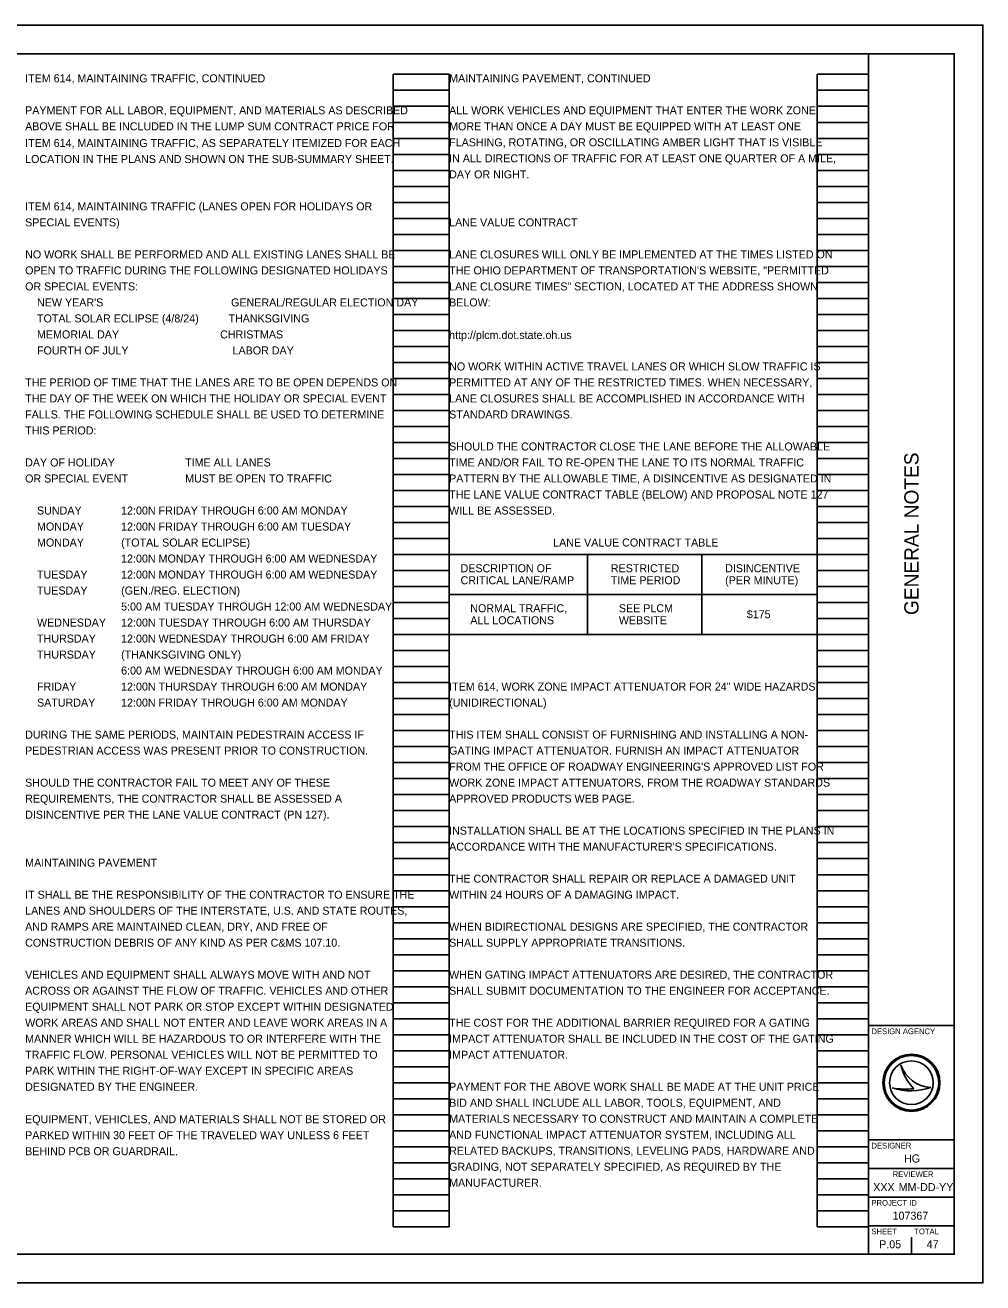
# Model space of a CAD drawing. Extents: x 0 to 34, y 0 to 22.
# Drawn here: x 17.24 to 34, y 0 to 22 of the extents above; entities that cross this region are included whole.
import ezdxf

# ---------------------------------------------------------------- set-up
doc = ezdxf.new("R2010")
doc.units = 0
for name, color, linetype in [('SH_Border', 7, 'Continuous'), ('SH_Cut_Line', 7, 'Continuous'), ('SH_Data', 7, 'Continuous'), ('SH_Text', 7, 'Continuous')]:
    doc.layers.add(name, color=color, linetype=linetype)

msp = doc.modelspace()

# ---------------------------------------------------------------- linework, layer by layer
at = {"layer": 'SH_Border'}
for p, q in [((32, 0.5), (32, 21.5)), ((32, 4.5), (33.5, 4.5)), ((32, 2.5), (33.5, 2.5)), ((32, 2), (33.5, 2)), ((32, 1.5), (33.5, 1.5)), ((32, 1), (33.5, 1))]:
    msp.add_line(p, q, dxfattribs=at)
msp.add_lwpolyline([(1.5, 21.5), (33.5, 21.5), (33.5, 0.5), (1.5, 0.5)], close=True, dxfattribs=at)
at = {"layer": 'SH_Cut_Line'}
msp.add_lwpolyline([(0, 0), (34, 0), (34, 22), (0, 22)], close=True, dxfattribs=at)
at = {"layer": 'SH_Data'}
for p, q in [((23.68, 0.98), (23.68, 21.14)), ((23.68, 21.14), (24.66, 21.14)), ((24.66, 0.98), (24.66, 21.14)), ((31.1, 0.98), (31.1, 21.14)), ((31.1, 21.14), (32, 21.14)), ((32, 0.98), (32, 21.14)), ((23.68, 20.86), (24.66, 20.86)), ((31.1, 20.86), (32, 20.86)), ((23.68, 20.58), (24.66, 20.58)), ((31.1, 20.58), (32, 20.58)), ((23.68, 20.3), (24.66, 20.3)), ((31.1, 20.3), (32, 20.3)), ((23.68, 20.02), (24.66, 20.02)), ((31.1, 20.02), (32, 20.02)), ((23.68, 19.74), (24.66, 19.74)), ((31.1, 19.74), (32, 19.74)), ((23.68, 19.46), (24.66, 19.46)), ((31.1, 19.46), (32, 19.46)), ((23.68, 19.18), (24.66, 19.18)), ((31.1, 19.18), (32, 19.18)), ((23.68, 18.9), (24.66, 18.9)), ((31.1, 18.9), (32, 18.9)), ((23.68, 18.62), (24.66, 18.62)), ((31.1, 18.62), (32, 18.62)), ((23.68, 18.34), (24.66, 18.34)), ((31.1, 18.34), (32, 18.34)), ((23.68, 18.06), (24.66, 18.06)), ((31.1, 18.06), (32, 18.06)), ((23.68, 17.78), (24.66, 17.78)), ((31.1, 17.78), (32, 17.78)), ((23.68, 17.5), (24.66, 17.5)), ((31.1, 17.5), (32, 17.5)), ((23.68, 17.22), (24.66, 17.22)), ((31.1, 17.22), (32, 17.22)), ((23.68, 16.94), (24.66, 16.94)), ((31.1, 16.94), (32, 16.94)), ((23.68, 16.66), (24.66, 16.66)), ((31.1, 16.66), (32, 16.66)), ((23.68, 16.38), (24.66, 16.38)), ((31.1, 16.38), (32, 16.38)), ((23.68, 16.1), (24.66, 16.1)), ((31.1, 16.1), (32, 16.1)), ((23.68, 15.82), (24.66, 15.82)), ((31.1, 15.82), (32, 15.82)), ((23.68, 15.54), (24.66, 15.54)), ((31.1, 15.54), (32, 15.54)), ((23.68, 15.26), (24.66, 15.26)), ((31.1, 15.26), (32, 15.26)), ((23.68, 14.98), (24.66, 14.98)), ((31.1, 14.98), (32, 14.98)), ((23.68, 14.7), (24.66, 14.7)), ((31.1, 14.7), (32, 14.7)), ((23.68, 14.42), (24.66, 14.42)), ((31.1, 14.42), (32, 14.42)), ((23.68, 14.14), (24.66, 14.14)), ((31.1, 14.14), (32, 14.14)), ((23.68, 13.86), (24.66, 13.86)), ((31.1, 13.86), (32, 13.86)), ((23.68, 13.58), (24.66, 13.58)), ((31.1, 13.58), (32, 13.58)), ((23.68, 13.3), (24.66, 13.3)), ((31.1, 13.3), (32, 13.3)), ((23.68, 13.02), (24.66, 13.02)), ((31.1, 13.02), (32, 13.02)), ((23.68, 12.74), (24.66, 12.74)), ((31.1, 12.74), (32, 12.74)), ((23.68, 12.46), (24.66, 12.46)), ((31.1, 12.46), (32, 12.46)), ((23.68, 12.18), (24.66, 12.18)), ((31.1, 12.18), (32, 12.18)), ((23.68, 11.9), (24.66, 11.9)), ((31.1, 11.9), (32, 11.9)), ((23.68, 11.62), (24.66, 11.62)), ((31.1, 11.62), (32, 11.62)), ((23.68, 11.34), (24.66, 11.34)), ((31.1, 11.34), (32, 11.34)), ((23.68, 11.06), (24.66, 11.06)), ((31.1, 11.06), (32, 11.06)), ((23.68, 10.78), (24.66, 10.78)), ((31.1, 10.78), (32, 10.78)), ((23.68, 10.5), (24.66, 10.5)), ((31.1, 10.5), (32, 10.5)), ((23.68, 10.22), (24.66, 10.22)), ((31.1, 10.22), (32, 10.22)), ((23.68, 9.94), (24.66, 9.94)), ((31.1, 9.94), (32, 9.94)), ((23.68, 9.66), (24.66, 9.66)), ((31.1, 9.66), (32, 9.66)), ((23.68, 9.38), (24.66, 9.38)), ((31.1, 9.38), (32, 9.38)), ((23.68, 9.1), (24.66, 9.1)), ((31.1, 9.1), (32, 9.1)), ((23.68, 8.82), (24.66, 8.82)), ((31.1, 8.82), (32, 8.82)), ((23.68, 8.54), (24.66, 8.54)), ((31.1, 8.54), (32, 8.54)), ((23.68, 8.26), (24.66, 8.26)), ((31.1, 8.26), (32, 8.26)), ((23.68, 7.98), (24.66, 7.98)), ((31.1, 7.98), (32, 7.98)), ((23.68, 7.7), (24.66, 7.7)), ((31.1, 7.7), (32, 7.7)), ((23.68, 7.42), (24.66, 7.42)), ((31.1, 7.42), (32, 7.42)), ((23.68, 7.14), (24.66, 7.14)), ((31.1, 7.14), (32, 7.14)), ((23.68, 6.86), (24.66, 6.86)), ((31.1, 6.86), (32, 6.86)), ((23.68, 6.58), (24.66, 6.58)), ((31.1, 6.58), (32, 6.58)), ((23.68, 6.3), (24.66, 6.3)), ((31.1, 6.3), (32, 6.3)), ((23.68, 6.02), (24.66, 6.02)), ((31.1, 6.02), (32, 6.02)), ((23.68, 5.74), (24.66, 5.74)), ((31.1, 5.74), (32, 5.74)), ((23.68, 5.46), (24.66, 5.46)), ((31.1, 5.46), (32, 5.46)), ((23.68, 5.18), (24.66, 5.18)), ((31.1, 5.18), (32, 5.18)), ((23.68, 4.9), (24.66, 4.9)), ((31.1, 4.9), (32, 4.9)), ((23.68, 4.62), (24.66, 4.62)), ((31.1, 4.62), (32, 4.62)), ((23.68, 4.34), (24.66, 4.34)), ((31.1, 4.34), (32, 4.34)), ((23.68, 4.06), (24.66, 4.06)), ((31.1, 4.06), (32, 4.06)), ((23.68, 3.78), (24.66, 3.78)), ((31.1, 3.78), (32, 3.78)), ((32.567, 3.81), (32.567, 3.81)), ((23.68, 3.5), (24.66, 3.5)), ((31.1, 3.5), (32, 3.5)), ((32.417, 3.41), (32.417, 3.41)), ((32.75, 3.5), (32.75, 3.5)), ((33.087, 3.419), (33.087, 3.419)), ((23.68, 3.22), (24.66, 3.22)), ((31.1, 3.22), (32, 3.22)), ((23.68, 2.94), (24.66, 2.94)), ((31.1, 2.94), (32, 2.94)), ((23.68, 2.66), (24.66, 2.66)), ((31.1, 2.66), (32, 2.66)), ((23.68, 2.38), (24.66, 2.38)), ((31.1, 2.38), (32, 2.38)), ((23.68, 2.1), (24.66, 2.1)), ((31.1, 2.1), (32, 2.1)), ((23.68, 1.82), (24.66, 1.82)), ((31.1, 1.82), (32, 1.82)), ((23.68, 1.54), (24.66, 1.54)), ((31.1, 1.54), (32, 1.54)), ((23.68, 1.26), (24.66, 1.26)), ((31.1, 1.26), (32, 1.26)), ((23.68, 0.98), (24.66, 0.98)), ((31.1, 0.98), (32, 0.98)), ((32.375, 0.675), (32.375, 0.675)), ((32.75, 0.5), (32.75, 0.8))]:
    msp.add_line(p, q, dxfattribs=at)
for radius in [0.5, 0.477, 0.477, 0.382]:
    msp.add_circle((32.75, 3.5), radius, dxfattribs=at)
for centre, radius, start, end in [((33.116, 3.998), 0.58, 198.9257, 198.9319), ((33.347, 3.97), 0.796, 191.6379, 191.6421), ((33.116, 3.998), 0.58, 198.9319, 267.1657), ((33.347, 3.97), 0.796, 191.6421, 226.0947), ((32.739, 4.37), 1.013, 251.4576, 290.0832), ((32.648, 4.654), 1.266, 259.4964, 259.4995), ((32.739, 4.37), 1.013, 251.4527, 251.4576), ((32.648, 4.654), 1.266, 259.4995, 276.6672)]:
    msp.add_arc(centre, radius, start, end, dxfattribs=at)
at = {"layer": 'SH_Text'}
for p, q in [((27.08, 12.74), (27.08, 11.34)), ((29.08, 12.74), (29.08, 11.34)), ((24.66, 12.04), (31.1, 12.04))]:
    msp.add_line(p, q, dxfattribs=at)
msp.add_lwpolyline([(24.66, 12.74), (31.1, 12.74), (31.1, 11.34), (24.66, 11.34)], close=True, dxfattribs=at)

# ---------------------------------------------------------------- texts
at = {"layer": 'SH_Data'}
msp.add_text('GENERAL NOTES', height=0.25, rotation=90, dxfattribs=at).set_placement((32.875, 11.682))
for s, height, p in [('DESIGN AGENCY', 0.1, (32.05, 4.35)), ('DESIGNER', 0.1, (32.05, 2.35)), ('HG', 0.14, (32.62, 2.105)), ('REVIEWER', 0.1, (32.422, 1.85)), ('XXX', 0.14, (32.081, 1.605)), ('MM-DD-YY', 0.14, (32.527, 1.605)), ('PROJECT ID', 0.1, (32.05, 1.35)), ('107367', 0.14, (32.42, 1.105)), ('SHEET', 0.1, (32.05, 0.85)), ('TOTAL', 0.1, (32.8, 0.85)), ('P.05', 0.14, (32.185, 0.605)), ('47', 0.14, (33.018, 0.605))]:
    msp.add_text(s, height=height, dxfattribs=at).set_placement(p)
at = {"layer": 'SH_Text'}
for s, p in [('ITEM 614, MAINTAINING TRAFFIC, CONTINUED', (17.24, 21)), ('MAINTAINING PAVEMENT, CONTINUED', (24.66, 21)), ('PAYMENT FOR ALL LABOR, EQUIPMENT, AND MATERIALS AS DESCRIBED', (17.24, 20.44)), ('ALL WORK VEHICLES AND EQUIPMENT THAT ENTER THE WORK ZONE', (24.66, 20.44)), ('ABOVE SHALL BE INCLUDED IN THE LUMP SUM CONTRACT PRICE FOR', (17.24, 20.16)), ('MORE THAN ONCE A DAY MUST BE EQUIPPED WITH AT LEAST ONE', (24.66, 20.16)), ('FLASHING, ROTATING, OR OSCILLATING AMBER LIGHT THAT IS VISIBLE', (24.66, 19.88)), ('ITEM 614, MAINTAINING TRAFFIC, AS SEPARATELY ITEMIZED FOR EACH', (17.24, 19.868)), ('LOCATION IN THE PLANS AND SHOWN ON THE SUB-SUMMARY SHEET.', (17.24, 19.588)), ('IN ALL DIRECTIONS OF TRAFFIC FOR AT LEAST ONE QUARTER OF A MILE,', (24.66, 19.6)), ('DAY OR NIGHT.', (24.66, 19.32)), ('ITEM 614, MAINTAINING TRAFFIC (LANES OPEN FOR HOLIDAYS OR', (17.24, 18.76)), ('SPECIAL EVENTS)', (17.24, 18.48)), ('LANE VALUE CONTRACT', (24.66, 18.48)), ('NO WORK SHALL BE PERFORMED AND ALL EXISTING LANES SHALL BE', (17.24, 17.92)), ('LANE CLOSURES WILL ONLY BE IMPLEMENTED AT THE TIMES LISTED ON', (24.66, 17.92)), ('OPEN TO TRAFFIC DURING THE FOLLOWING DESIGNATED HOLIDAYS', (17.24, 17.64)), ('THE OHIO DEPARTMENT OF TRANSPORTATION\'S WEBSITE, "PERMITTED', (24.66, 17.64)), ('OR SPECIAL EVENTS:', (17.24, 17.36)), ('LANE CLOSURE TIMES" SECTION, LOCATED AT THE ADDRESS SHOWN', (24.66, 17.36)), ("    NEW YEAR'S                                           GENERAL/REGULAR ELECTION DAY", (17.24, 17.08)), ('BELOW:', (24.66, 17.08)), ('    TOTAL SOLAR ECLIPSE (4/8/24)          THANKSGIVING', (17.24, 16.8)), ('    MEMORIAL DAY                  ', (17.24, 16.52)), (' CHRISTMAS', (20.6, 16.52)), ('http://plcm.dot.state.oh.us', (24.66, 16.51)), ('    FOURTH OF JULY                                   LABOR DAY', (17.24, 16.24)), ('NO WORK WITHIN ACTIVE TRAVEL LANES OR WHICH SLOW TRAFFIC IS', (24.66, 15.96)), ('THE PERIOD OF TIME THAT THE LANES ARE TO BE OPEN DEPENDS ON', (17.24, 15.68)), ('PERMITTED AT ANY OF THE RESTRICTED TIMES. WHEN NECESSARY,', (24.66, 15.68)), ('THE DAY OF THE WEEK ON WHICH THE HOLIDAY OR SPECIAL EVENT', (17.24, 15.4)), ('LANE CLOSURES SHALL BE ACCOMPLISHED IN ACCORDANCE WITH', (24.66, 15.4)), ('FALLS. THE FOLLOWING SCHEDULE SHALL BE USED TO DETERMINE', (17.24, 15.12)), ('STANDARD DRAWINGS.', (24.66, 15.12)), ('THIS PERIOD:', (17.24, 14.84)), ('SHOULD THE CONTRACTOR CLOSE THE LANE BEFORE THE ALLOWABLE', (24.66, 14.56)), ('DAY OF HOLIDAY', (17.24, 14.28)), ('TIME ALL LANES', (20.04, 14.28)), ('TIME AND/OR FAIL TO RE-OPEN THE LANE TO ITS NORMAL TRAFFIC', (24.66, 14.28)), ('OR SPECIAL EVENT', (17.24, 14)), ('MUST BE OPEN TO TRAFFIC', (20.04, 14)), ('PATTERN BY THE ALLOWABLE TIME, A DISINCENTIVE AS DESIGNATED IN', (24.66, 14)), ('THE LANE VALUE CONTRACT TABLE (BELOW) AND PROPOSAL NOTE 127', (24.66, 13.72)), ('    SUNDAY', (17.24, 13.44)), ('12:00N FRIDAY THROUGH 6:00 AM MONDAY', (18.92, 13.44)), ('WILL BE ASSESSED.', (24.66, 13.44)), ('    MONDAY', (17.24, 13.16)), ('12:00N FRIDAY THROUGH 6:00 AM TUESDAY', (18.92, 13.16)), ('    MONDAY', (17.24, 12.88)), ('(TOTAL SOLAR ECLIPSE)', (18.92, 12.88)), ('                                   LANE VALUE CONTRACT TABLE', (24.66, 12.88)), ('12:00N MONDAY THROUGH 6:00 AM WEDNESDAY', (18.92, 12.6)), ('DESCRIPTION OF', (24.86, 12.43)), ('RESTRICTED', (27.49, 12.43)), ('DISINCENTIVE', (29.49, 12.43)), ('    TUESDAY', (17.24, 12.32)), ('12:00N MONDAY THROUGH 6:00 AM WEDNESDAY', (18.92, 12.32)), ('CRITICAL LANE/RAMP', (24.86, 12.22)), ('TIME PERIOD', (27.49, 12.22)), ('(PER MINUTE)', (29.49, 12.22)), ('    TUESDAY', (17.24, 12.04)), ('(GEN./REG. ELECTION)', (18.92, 12.04)), ('5:00 AM TUESDAY THROUGH 12:00 AM WEDNESDAY', (18.92, 11.76)), ('ALL LOCATIONS', (25.03, 11.52)), ('NORMAL TRAFFIC,', (25.03, 11.73)), ('WEBSITE', (27.63, 11.52)), ('SEE PLCM', (27.63, 11.73)), ('$175', (29.869, 11.625)), ('    WEDNESDAY', (17.24, 11.48)), ('12:00N TUESDAY THROUGH 6:00 AM THURSDAY', (18.92, 11.48)), ('    THURSDAY', (17.24, 11.2)), ('12:00N WEDNESDAY THROUGH 6:00 AM FRIDAY', (18.92, 11.2)), ('    THURSDAY', (17.24, 10.92)), ('(THANKSGIVING ONLY)', (18.92, 10.92)), ('6:00 AM WEDNESDAY THROUGH 6:00 AM MONDAY', (18.92, 10.64)), ('    FRIDAY', (17.24, 10.36)), ('12:00N THURSDAY THROUGH 6:00 AM MONDAY', (18.92, 10.36)), ('ITEM 614, WORK ZONE IMPACT ATTENUATOR FOR 24" WIDE HAZARDS', (24.66, 10.36)), ('    SATURDAY', (17.24, 10.08)), ('12:00N FRIDAY THROUGH 6:00 AM MONDAY', (18.92, 10.08)), ('(UNIDIRECTIONAL)', (24.66, 10.08)), ('DURING THE SAME PERIODS, MAINTAIN PEDESTRAIN ACCESS IF', (17.24, 9.52)), ('THIS ITEM SHALL CONSIST OF FURNISHING AND INSTALLING A NON-', (24.66, 9.52)), ('PEDESTRIAN ACCESS WAS PRESENT PRIOR TO CONSTRUCTION.', (17.24, 9.24)), ('GATING IMPACT ATTENUATOR. FURNISH AN IMPACT ATTENUATOR', (24.66, 9.24)), ("FROM THE OFFICE OF ROADWAY ENGINEERING'S APPROVED LIST FOR", (24.66, 8.96)), ('SHOULD THE CONTRACTOR FAIL TO MEET ANY OF THESE', (17.24, 8.68)), ('WORK ZONE IMPACT ATTENUATORS, FROM THE ROADWAY STANDARDS', (24.66, 8.68)), ('REQUIREMENTS, THE CONTRACTOR SHALL BE ASSESSED A', (17.24, 8.4)), ('APPROVED PRODUCTS WEB PAGE.', (24.66, 8.4)), ('DISINCENTIVE PER THE LANE VALUE CONTRACT (PN 127).', (17.24, 8.12)), ('INSTALLATION SHALL BE AT THE LOCATIONS SPECIFIED IN THE PLANS IN', (24.66, 7.84)), ("ACCORDANCE WITH THE MANUFACTURER'S SPECIFICATIONS.", (24.66, 7.56)), ('MAINTAINING PAVEMENT', (17.24, 7.28)), ('THE CONTRACTOR SHALL REPAIR OR REPLACE A DAMAGED UNIT', (24.66, 7)), ('IT SHALL BE THE RESPONSIBILITY OF THE CONTRACTOR TO ENSURE THE', (17.24, 6.72)), ('WITHIN 24 HOURS OF A DAMAGING IMPACT.', (24.66, 6.72)), ('LANES AND SHOULDERS OF THE INTERSTATE, U.S. AND STATE ROUTES,', (17.24, 6.44)), ('AND RAMPS ARE MAINTAINED CLEAN, DRY, AND FREE OF', (17.24, 6.16)), ('WHEN BIDIRECTIONAL DESIGNS ARE SPECIFIED, THE CONTRACTOR', (24.66, 6.16)), ('CONSTRUCTION DEBRIS OF ANY KIND AS PER C&MS 107.10.', (17.24, 5.88)), ('SHALL SUPPLY APPROPRIATE TRANSITIONS.', (24.66, 5.88)), ('VEHICLES AND EQUIPMENT SHALL ALWAYS MOVE WITH AND NOT', (17.24, 5.32)), ('WHEN GATING IMPACT ATTENUATORS ARE DESIRED, THE CONTRACTOR', (24.66, 5.32)), ('ACROSS OR AGAINST THE FLOW OF TRAFFIC. VEHICLES AND OTHER', (17.24, 5.04)), ('SHALL SUBMIT DOCUMENTATION TO THE ENGINEER FOR ACCEPTANCE.', (24.66, 5.04)), ('EQUIPMENT SHALL NOT PARK OR STOP EXCEPT WITHIN DESIGNATED', (17.24, 4.76)), ('WORK AREAS AND SHALL NOT ENTER AND LEAVE WORK AREAS IN A', (17.24, 4.48)), ('THE COST FOR THE ADDITIONAL BARRIER REQUIRED FOR A GATING', (24.66, 4.48)), ('MANNER WHICH WILL BE HAZARDOUS TO OR INTERFERE WITH THE', (17.24, 4.2)), ('IMPACT ATTENUATOR SHALL BE INCLUDED IN THE COST OF THE GATING', (24.66, 4.2)), ('TRAFFIC FLOW. PERSONAL VEHICLES WILL NOT BE PERMITTED TO', (17.24, 3.92)), ('IMPACT ATTENUATOR.', (24.66, 3.92)), ('PARK WITHIN THE RIGHT-OF-WAY EXCEPT IN SPECIFIC AREAS', (17.24, 3.64)), ('DESIGNATED BY THE ENGINEER.', (17.24, 3.36)), ('PAYMENT FOR THE ABOVE WORK SHALL BE MADE AT THE UNIT PRICE', (24.66, 3.36)), ('BID AND SHALL INCLUDE ALL LABOR, TOOLS, EQUIPMENT, AND', (24.66, 3.08)), ('EQUIPMENT, VEHICLES, AND MATERIALS SHALL NOT BE STORED OR', (17.24, 2.793)), ('MATERIALS NECESSARY TO CONSTRUCT AND MAINTAIN A COMPLETE', (24.66, 2.8)), ('PARKED WITHIN 30 FEET OF THE TRAVELED WAY UNLESS 6 FEET', (17.24, 2.513)), ('AND FUNCTIONAL IMPACT ATTENUATOR SYSTEM, INCLUDING ALL', (24.66, 2.52)), ('BEHIND PCB OR GUARDRAIL.', (17.24, 2.233)), ('RELATED BACKUPS, TRANSITIONS, LEVELING PADS, HARDWARE AND', (24.66, 2.24)), ('GRADING, NOT SEPARATELY SPECIFIED, AS REQUIRED BY THE', (24.66, 1.96)), ('MANUFACTURER.', (24.66, 1.68))]:
    msp.add_text(s, height=0.14, dxfattribs=at).set_placement(p)

doc.saveas('drawing.dxf')
